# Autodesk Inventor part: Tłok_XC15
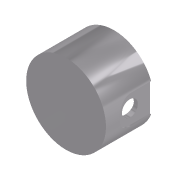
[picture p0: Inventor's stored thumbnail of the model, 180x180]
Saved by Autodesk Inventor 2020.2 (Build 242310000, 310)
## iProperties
Created: 2000-05
Part Number: Tłok_XC15
Document SubType Name: Modeling
Designer: F.Stasiak
Stock Number: Tłok_XC15
Density: 2.7 g/cm^3
Material: Aluminium 6061
Appearance: Aluminium (polerowane)
Mass: 554.321 g
Surface Area: 467.71 cm^2
Volume: 205.304 cm^3
Catalog Web Link: www.expertbooks.pl
Manager: www.cadconsulting.pl
Company: Fabian Stasiak CAD Consulting
Control State: 0
Master: False
Checked Out: False
Shininess: 0.0
Density: 0.0
Volumn: 0.0
Area: 0.0
PropertySet Name: Model Information
Author: F.Stasiak
Subject: Zbiór ćwiczeń. Autodesk Inventor 2020. Kurs Professional
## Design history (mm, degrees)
node "Base1"
node "Płaszczyzna konstrukcyjna1"
node "Edytuj bezpośrednio1"
node "Płaszczyzna konstrukcyjna3"
  node "Płaszczyzna konstrukcyjna2"
sketch "Szkic4" dims "d11" = 8
  geometry: L1 (0, -50)-(0, 50) reference; L2 (25, -18)-(0, -18); L3 (25, 18)-(0, 18); 3 further points
  constraints: 4 end point, 2 point on line, 1 horizontal, 1 perpendicular, 1 vertical alignment, 4 other
extrude "Wyciągnięcie proste4" cut sketch "Szkic4" extent not by distance; stored distance "d12" = 12; taper "d13" = 0 deg
mirror "Odbicie lustrzane2"
node "Bryła1"
node "Korpusy bryłowe"
node "Korpusy powierzchniowe"
node "Oś konstrukcyjna1"
node "Pętla rzutowana3"
feature "Usuń1"
other parameters: "d0" = 25, "d9" = 0, "d10" = 45
